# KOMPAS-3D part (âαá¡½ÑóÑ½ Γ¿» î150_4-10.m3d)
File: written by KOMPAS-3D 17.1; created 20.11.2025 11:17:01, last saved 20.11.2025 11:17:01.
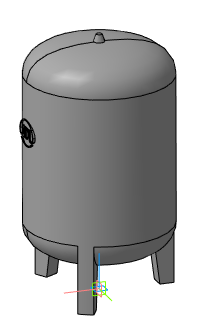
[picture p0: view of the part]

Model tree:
1. Операция без истории:4

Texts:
  REVIT MATERIAL OVERRIDDEN
  REVIT MATERIAL ID
  REVIT SUBCATEGORY ID
  REVIT CATEGORY ID
  REVIT ELEMENT ID
  REVIT BREP TAG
